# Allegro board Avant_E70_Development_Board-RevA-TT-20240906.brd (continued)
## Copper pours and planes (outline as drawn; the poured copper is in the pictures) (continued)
VCC_AUX on L12-SIG4: 72.96,83.32 73.8,84.17 74.37,84.17 74.93,83.6 75.27,83.6 75.51,83.36 75.51,81.32 76.34,80.5 80.02,80.5 80.82,81.3 80.82,95.38 82.03,96.58 82.03,99.48 83.12,100.57 83.12,120.76 83.82,121.46 100.97,121.46 101.85,120.57 101.85,115.74 100.33,114.22 91.69,114.22 90.3,112.82 90.3,103.81 90.68,103.42 90.68,91.99 84.71,86.03 84.71,78.79 81.38,75.45 73.7,75.45 72.96,76.19
VCC_AUX_IN on BOTTOM: 98.04,119.93 101.09,119.93 101.47,119.55 101.47,118.03 101.09,117.65 97.92,117.65 97.79,117.78 97.79,119.68
VCC_CORE on TOP: 107.42,94.07 107.41,94.06 106.71,94.06 106.43,93.77 106.43,86.91 106.68,86.66 119.51,86.66 119.76,86.91 119.76,93.77 119.46,94.07
VCC_CORE on BOTTOM: 75.06,75.1 74.93,75.23 74.04,75.23 73.79,75.48 73.79,79.29 74.55,80.06 74.55,81.71 75.95,83.1 80.52,83.1 82.04,84.63 82.04,92.63 83.19,93.77 100.58,93.77 103.25,91.11 106.17,91.11 106.43,91.36 106.43,93.77 106.63,93.97 114.35,93.97 114.55,93.77 114.55,91.11 112.9,89.45 112.14,89.45 110.49,87.8 98.81,87.8 92.84,81.83 89.92,81.83 89.15,81.07 89.15,79.68 88.14,78.66 87.38,78.66 86.61,77.9 86.61,77.14 86.36,77.14 86.36,75.74 85.72,75.1 ; 5 cut-outs
VCC_CORE on L03-SIG1: 114.68,94.03 107.44,94.03 107.19,93.77 107.19,89.84 107.44,89.58 114.55,89.58 114.94,89.96 114.94,93.77
VCC_CORE on L07_POW1: 75.32,77.14 75.32,89.91 75.32,89.91 75.32,92.56 77.04,94.28 77.22,94.28 77.85,94.92 111.12,94.92 111.76,94.28 114.17,94.28 114.55,93.9 114.55,91.11 111.89,88.44 111.89,86.03 111.38,85.52 107.19,85.52 105.79,84.12 105.79,64.44 104.52,63.17 78.74,63.17 77.85,64.05 77.85,75.1 77.72,75.23 74.68,75.23 74.55,75.36 74.55,76.37 74.55,76.37
VCC_DDR on TOP: 92.33,117.78 92.33,119.3 92.71,119.68 96.65,119.68 96.9,119.43 96.9,117.78 96.52,117.39 92.71,117.39
VCC_DDR on BOTTOM: 124.4,92.95 124.27,93.07 124.27,95.11 124.4,95.23 126.05,95.23 126.17,95.11 126.17,93.07 126.05,92.95
VCC_DDR on L07_POW1: 106.81,84.5 106.81,60.63 107.44,59.99 122.17,59.99 124.21,62.02 124.21,89.71 126.62,92.12 126.62,94.79 126.24,95.17 123.44,95.17 122.17,96.44 122.17,100.88 121.28,101.77 116.84,101.77 102.24,116.38 99.31,116.38 96.39,119.3 93.6,119.3 91.82,117.52 91.82,97.2 93.6,95.42 111.25,95.42 112.4,94.28 112.4,85.52 112.01,85.14 107.44,85.14
VCC_DDR_VDD1 on BOTTOM: 119.51,88.95 119.38,89.07 116.97,89.07 116.59,88.69 116.59,87.3 116.71,87.17 119.38,87.17 119.51,87.3
VCC_DDR_VDD1 on L08-POW2: 112.78,88.57 107.95,83.74 107.95,58.85 108.84,57.96 123.32,57.96 124.97,59.61 124.97,84.12 120.52,88.57
VCCA_PLL4 on TOP: 115.19,109.77 118.62,109.77 119.25,109.14 119.25,106.73 119,106.47 114.81,106.47 114.81,109.39
VCCA_PLL4 on BOTTOM: 114.94,110.41 114.94,107.36 115.32,106.98 117.86,106.98 118.24,107.36 118.24,109.52 117.35,110.41
VCCA_PLL4 on L10-SIG3: 77.77,76.11 77.77,77.99 78.76,78.98 80.95,78.98 81.54,79.57 81.54,86.9 85.58,90.93 103.56,90.93 106.48,93.85 106.48,97.25 113.41,104.19 113.41,105.33 113.92,105.84 117.09,105.84 117.6,106.35 117.6,109.52 117.22,109.9 111.51,109.9 106.17,104.57 104.52,104.57 102.41,102.46 102.41,97.71 100.46,95.76 100.46,94.61 99.95,94.1 98.56,94.1 98.32,94.35 83.66,94.35 77.91,88.6 77.91,82.61 77.25,81.96 76.48,81.96 75.44,80.92 75.44,75.87 75.63,75.68 77.34,75.68
VCCA_PLL4_IN on BOTTOM: 110.49,108.76 110.49,107.11 110.74,106.85 113.79,106.85 114.05,107.11 114.05,110.28 113.79,110.54 113.28,110.54 111.89,109.14 110.87,109.14
VCCA_PLL7 on TOP: 115.06,105.08 119,105.08 119.25,104.82 119.25,101.77 119,101.52 115.06,101.52 114.81,101.77 114.81,104.82
VCCA_PLL7 on BOTTOM: 115.06,106.09 115.06,102.41 115.44,102.03 118.11,102.03 118.24,102.15 118.24,105.96 117.98,106.22 115.19,106.22
VCCA_PLL7 on L10-SIG3: 103.96,90.58 85.85,90.58 82.18,86.91 82.18,79.75 81.1,78.68 78.9,78.68 78.15,77.93 78.15,76.78 78.59,76.35 83.23,76.35 83.68,76.79 83.68,79.36 84.64,80.32 84.64,86.02 86.52,87.9 111.73,87.9 113.86,90.03 113.86,98.54 117.98,102.66 117.98,104.95 117.35,105.58 114.3,105.58 113.66,104.95 113.66,103.81 108.12,98.26 108.12,98.22 107.06,97.16 107.06,97.07 106.81,96.82 106.81,93.43
VCCA_PLL7_IN on BOTTOM: 114.3,102.79 113.79,102.28 110.87,102.28 110.49,102.66 110.49,105.84 111,106.35 114.17,106.35 114.3,106.22
VCCA_PLL10 on TOP: 106.55,53.64 106.55,47.67 106.81,47.42 109.47,47.42 109.6,47.54 109.6,50.59 109.09,51.1 109.09,53.51 108.84,53.77 106.68,53.77
VCCA_PLL10 on BOTTOM: 86.92,75.54 86.92,71.62 87.95,70.6 87.95,69.58 90.04,67.48 90.04,65.88 91.11,64.82 91.11,62.05 97.28,55.88 104.75,55.88 106.93,53.69 106.93,51.35 107.16,51.13 108.66,51.13 108.76,51.23 108.76,53.84 105.38,57.22 98.98,57.22 93.8,62.4 93.8,67.89 93.78,67.92 93.78,69.82 92.61,70.99 90.91,70.99 89.79,72.11 89.79,75.41 89.5,75.7 88.66,75.7 88.11,76.25 87.22,76.25 87.21,76.23 86.83,76.23 86.66,76.07 86.66,75.79
VCCA_PLL10_IN on TOP: 109.98,51.74 109.98,47.67 110.24,47.42 111.89,47.42 112.27,47.8 112.27,49.58 111.76,50.08 111.76,51.74 111.63,51.86 110.11,51.86
VCCA_PLLW on TOP: 101.13,96.66 101.13,96.21 100.84,95.91 100.84,93.44 100.75,93.35 98.82,93.35 98.69,93.47 98.69,99.41 99.23,99.95 102.37,99.95 102.54,99.79 102.54,98.07
VCCA_PLLW on BOTTOM: 98.76,94.49 99.95,94.49 99.97,94.51 101.07,94.51 101.35,94.79 101.35,96.57 102.24,97.46 102.24,99.36 101.85,99.74 98.93,99.74 98.66,99.47 98.66,94.59
VCCA_PLLW on L10-SIG3: 74.5,84.17 75.07,84.74 75.07,91.96 79.95,96.84 79.95,101 81.33,102.38 98.85,102.38 98.87,102.35 101.56,102.35 101.99,101.91 101.99,97.79 100.13,95.93 100.13,94.63 99.98,94.48 98.64,94.48 98.34,94.78 83.36,94.78 77.38,88.79 77.38,83.65 77.22,83.49 74.8,83.49 74.5,83.79
VCCA_PLLW_IN on TOP: 101.73,93.16 104.51,93.16 104.76,93.41 104.76,94.41 104.66,94.51 101.64,94.51 101.6,94.46 101.6,93.29
VCCA_PLLW_IN on L12-SIG4: 102.69,99.47 106.9,99.47 107.32,99.04 107.32,93.21 106.61,92.51 102.31,92.51 102.04,92.77 102.04,98.82
VCCIO0 on TOP: 46.14,102.11 46.14,108.37 46.52,108.75 47.99,108.75 48.28,108.46 48.28,102.08 48.16,101.97 46.28,101.97
VCCIO0 on L12-SIG4: 64.52,79.04 53.39,79.04 48.56,83.87 48.56,98.15 45.91,100.8 45.91,108.58 46.51,109.18 52.89,109.18 53.46,108.61 53.46,85.77 56.76,82.47 67.82,82.47 68.39,83.04 68.39,84.95 68.87,85.42 73.11,85.42 73.97,86.28 75.23,86.28 75.38,86.14 75.38,84.46 75.3,84.37 73.77,84.37 72.63,83.24 72.63,79.03 72.26,78.66 64.9,78.66
VCCIO1 on TOP: 90.56,105.46 92.75,105.46 94.13,106.84 95.54,106.84 95.77,106.61 95.77,103.01 94.75,101.99 90.6,101.99 90.36,102.23 90.36,105.26
VCCIO1 on BOTTOM: 77.22,98.73 78.33,98.73 78.64,99.03 79.53,99.03 79.65,98.9 79.65,97.25 79.53,97.13 77.24,97.13 77.14,97.23 77.14,98.65
VCCIO1 on L10-SIG3: 70.83,84.46 69.98,85.31 69.52,85.31 69.29,85.54 69.29,99.95 75.27,105.93 75.27,109.35 75.61,109.69 99.53,109.69 100.08,109.14 100.08,103.93 99.04,102.9 80.98,102.9 79.32,101.25 79.32,97.18 74.45,92.31 74.45,84.94 73.97,84.46
VCCIO1_IN on TOP: 90.58,106.17 90.55,106.2 90.55,110.21 90.89,110.55 95.68,110.55 95.86,110.37 95.86,107.64 95.58,107.36 94.01,107.36 92.82,106.17
VCCIO1_IN on BOTTOM: 56.13,137.21 59.82,137.21 60.07,137.46 60.07,139.24 59.94,139.37 56.01,139.37 55.88,139.24 55.88,137.46
VCCIO1_IN on L05-SIG2: 49.49,129.3 46.61,126.41 46.61,120.06 45.59,119.05 45.59,116.76 48.5,113.85 50.18,113.85 50.7,113.33 59,113.33 59.74,114.07 59.74,120.24 61.34,121.84 61.34,124.58 60.58,125.35 60.58,134.62 60.56,134.64 60.56,138.25 59.94,138.86 50.16,138.86 49.49,138.19
VCCIO1_IN on L10-SIG3: 55.78,137.08 56.15,136.71 59.93,136.71 61.46,135.19 152.28,135.19 157.48,140.38 157.48,146 155.63,147.85 64.49,147.85 60.58,143.94 58.29,143.94 55.78,141.42
VCCIO1_IN on L12-SIG4: 132.21,100.76 155.85,100.76 156.21,100.39 163.47,100.39 164.19,101.11 164.19,146.32 161.07,149.44 136.44,149.44 135.42,148.42 135.42,145.27 137.66,143.02 144.93,143.02 145.1,142.86 151.57,142.86 153.29,141.14 153.29,123.21 147.09,117.01 128.02,117.01 125.6,114.6 101.47,114.6 100.71,113.84 91.88,113.84 91.44,113.4 91.31,113.4 90.68,112.76 90.68,106.73 91.19,106.22 101.85,106.22 102.36,106.73 106.04,106.73 106.55,106.22 110.36,106.22 111.51,105.08 127.89,105.08
VCCIO2 on TOP: 58.29,86.64 56.87,86.64 56.54,86.3 56.54,81.05 56.77,80.82 58.29,80.82 58.67,81.2 58.67,86.25
VCCIO2 on BOTTOM: 64.7,82.49 67.45,82.49 67.53,82.56 67.53,83.09 67.41,83.22 64.75,83.22 64.62,83.08 64.62,82.57
VCCIO2 on L12-SIG4: 61.88,118.83 62.49,118.22 62.49,111.6 63.84,110.25 69.28,110.25 71.56,107.97 71.56,99.07 73.5,97.13 73.5,86.19 73,85.7 72.57,85.7 72.12,86.14 68.9,86.14 67.92,85.16 67.92,82.96 67.69,82.72 67.18,82.72 67.17,82.71 57.52,82.71 54.08,86.15 54.08,108.9 52.51,110.46 40.23,110.46 39.55,111.14 39.55,118.13 40.24,118.83
VCCIO2_IN on TOP: 55.94,86.5 55.94,82.65 55.76,82.47 54.33,82.47 53.85,82.95 53.85,86.28 54.11,86.54 55.89,86.54
VCCIO2_IN on BOTTOM: 53.59,86.41 53.59,85.64 53.47,85.52 49.15,85.52 41.27,93.39 41.27,110.16 40.2,111.24 40.2,117.71 42.04,119.55 42.04,126.41 46.61,130.98 46.61,134.16 46.48,134.29 45.34,134.29 45.21,134.16 45.21,132.63 40.26,127.68 40.26,120.44 38.42,118.6 38.42,114.16 38.35,114.09 38.35,89.96 46.35,81.96 55.5,81.96 56.01,82.47 56.01,86.28 55.63,86.66 53.85,86.66
VCCIO3 on TOP: 68.37,113.6 68.37,114.99 69.08,115.7 69.08,116.67 69.3,116.89 75.07,116.89 75.3,116.67 75.3,113.7 74.72,113.13 68.84,113.13
VCCIO3 on L08-POW2: 59.37,73.39 59.03,73.72 59.03,90.34 55.88,93.5 55.88,110.03 56.84,110.99 59.89,110.99 65.73,116.83 75.1,116.83 75.3,116.64 75.3,110.33 75.28,110.31 75.28,108.09 74.68,107.49 65.28,107.49 64.52,106.73 64.52,98.99 68.43,95.08 68.43,80.33 68.83,79.93 73.13,79.93 74.14,78.92 74.14,73.7 73.83,73.39
VCCIO3_IN on TOP: 72.38,133.14 71.88,132.63 71.88,121.71 70.74,120.57 70.72,120.57 70.72,117.92 71.01,117.63 74.94,117.63 75.02,117.7 75.02,119.17 75.18,119.34 75.18,132.89 74.94,133.14
VCCIO4 on TOP: 75.86,113.58 75.86,116.66 76.23,117.02 82.41,117.02 82.69,116.74 82.69,113.7 82.11,113.11 76.33,113.11
VCCIO4 on BOTTOM: 65.29,98.39 67.48,98.39 67.73,98.64 67.73,99.62 67.63,99.72 65.13,99.72 65.03,99.62 65.03,98.64
VCCIO4 on L07_POW1: 62.29,63.44 61.67,64.05 61.67,111.94 66.76,117.03 82.41,117.03 82.7,116.74 82.7,113.99 81.27,112.56 72.83,112.56 68.94,108.67 68.94,74.33 71.42,71.85 71.42,68.69 71.17,68.43 68.78,68.43 68.52,68.17 68.52,63.6 68.35,63.44
VCCIO4_IN on TOP: 79.47,133.14 81.5,133.14 81.51,133.12 82.45,133.12 82.68,132.89 82.68,118.03 82.27,117.63 77.17,117.63 76.97,117.83 76.97,118.99 79.37,121.4 79.37,133.04
VCCIO5 on TOP: 86.12,113.7 90.99,113.7 91.25,113.96 91.25,116.7 90.99,116.95 86.12,116.95 85.87,116.7 85.87,113.96
VCCIO5 on BOTTOM: 72.82,97.26 74.35,97.26 74.6,97.51 74.6,98.5 74.35,98.75 72.61,98.75 72.56,98.71 72.56,97.51
VCCIO5 on L07_POW1: 69.43,63.52 69.43,67.27 69.65,67.49 71.03,67.49 72.33,68.8 72.33,71.84 69.36,74.82 69.36,108.26 73.06,111.96 81.53,111.96 83.16,113.59 83.16,116.77 83.42,117.02 90.42,117.02 90.81,116.63 90.81,96.69 89.53,95.42 77.21,95.42 74.61,92.82 74.61,76.97 73.77,76.13 73.77,75.38 74.29,74.85 77.22,74.85 77.6,74.47 77.6,63.73 77.25,63.38 69.57,63.38
VCCIO5_IN on TOP: 88.74,133.14 91.57,133.14 91.82,132.89 91.82,117.9 91.38,117.46 86.3,117.46 86.3,119.06 88.64,121.4 88.64,133.04
VCCIO6 on TOP: 114.31,110.29 114.31,114.71 114.03,114.98 110.49,114.98 110.11,114.6 110.11,110.41 110.49,110.03 114.05,110.03
VCCIO6 on BOTTOM: 114.3,114.98 110.49,114.98 110.11,114.6 110.11,110.28 110.36,110.03 111.76,110.03 112.9,111.17 114.3,111.17 114.43,111.3 114.43,114.85
VCCIO6 on BOTTOM: 77.42,68.6 78.62,68.6 78.82,68.4 78.82,65.74 78.6,65.53 77.86,65.53 77.66,65.72 77.66,66.46 78,66.8 78,67.36 77.42,67.95
VCCIO6 on L08-POW2: 74.38,73.03 74.72,73.37 80.55,73.37 80.79,73.12 80.79,60.83 84.25,57.37 100.99,57.37 102.87,59.25 102.87,84.24 105.66,87.04 105.66,106.65 105.77,106.75 105.77,108.48 110.36,113.08 114.81,113.08 115.32,112.57 115.32,91.87 107.44,83.99 107.44,55.93 104.14,52.62 80.09,52.62 74.38,58.33
VCCIO6_IN on TOP: 126.68,107.2 126.68,131.04 125.71,132.01 119.4,132.01 118.51,131.12 118.51,115.76 117.86,115.11 115.32,115.11 115.06,114.85 115.06,110.41 115.25,110.22 119.19,110.22 119.95,109.46 119.95,107.87 120.62,107.2
VCCIO6_IN on BOTTOM: 50.93,49.32 60.71,49.32 62.1,47.93 62.1,45.26 73.41,33.96 105.92,33.96 107.31,35.35 109.22,35.35 109.22,33.07 108.71,32.56 72.01,32.56 57.53,47.04 50.93,47.04 50.67,47.29 50.67,49.07
VCCIO6_IN on BOTTOM: 119.89,102.79 119.63,103.04 119.63,109.39 118.24,110.79 115.44,110.79 115.06,111.17 115.06,114.98 115.57,115.49 117.86,115.49 119,116.63 119,131.11 119.51,131.62 123.57,131.62 124.08,131.11 124.08,103.04 123.82,102.79
VCCIO6_IN on L03-SIG1: 124.64,102.33 124.21,101.9 115.04,101.9 114.27,102.66 114.27,110.38 118.82,114.93 118.82,122.04 121.79,125.01 124.08,125.01 124.64,124.46
VCCIO6_IN on L03-SIG1: 111.12,40.31 111.38,40.05 111.38,33.57 111.25,33.45 106.93,33.45 106.81,33.57 106.81,40.05 107.06,40.31
VCCIO6_IN on L12-SIG4: 60.54,46.95 59.84,46.25 38.97,46.25 38.38,45.66 6.13,45.66 0.52,51.28 0.52,113.21 3.42,116.12 13.1,116.12 13.16,116.05 15.78,116.05 18.27,118.54 18.27,123.85 27.27,132.85 65.47,132.85 72.98,140.35 116.26,140.35 124.83,131.78 124.83,125.75 123.46,124.38 123.44,124.38 123.44,115.74 122.94,115.24 119.38,115.24 118.87,115.74 118.87,123.24 116.54,125.57 116.54,125.85 110.04,132.35 73.57,132.35 64.39,123.18 36.26,123.18 31.64,118.55 31.64,117 21.29,106.65 5.71,106.65 4.61,105.55 4.61,63.17 14.29,53.48 18.3,53.48 19.91,55.09 58.73,55.09 60.54,53.28
VCCIO7 on TOP: 103.92,115.74 108.79,115.74 109.04,115.99 109.04,118.73 108.79,118.98 103.92,118.98 103.66,118.73 103.66,115.99
VCCIO7 on BOTTOM: 80.21,73.86 81.03,73.86 81.36,73.53 84.71,73.53 87.53,70.71 87.53,66.53 86.56,65.57 86.07,65.57 86.06,65.58 85.34,65.58 85.09,65.32 83.69,65.32 83.44,65.58 82.8,65.58 82.69,65.69 82.69,69.6 82.68,69.62 82.42,69.62 82.42,69.9 80.04,72.28 80.04,73.68
VCCIO7 on L05-SIG2: 82.55,70.68 83.07,70.16 83.07,68.75 83.06,68.75 82.8,68.5 81.28,68.5 80.77,69.01 80.77,78.58 82.12,79.93 82.12,80.03 82.42,80.34 82.42,97.61 85.5,100.69 85.5,100.7 88.01,103.21 88.01,118.92 88.77,119.68 108.33,119.68 109.47,118.54 109.47,112.31 108.97,111.81 101.35,111.81 99.57,110.03 99.57,102.98 87.44,90.85 87.44,81.64 85.53,79.74 85.53,78.72 82.55,75.74
VCCIO7_IN on TOP: 104.43,119.66 104.36,119.73 104.36,121.35 106.44,123.43 106.44,132.65 106.81,133.02 109.73,133.02 109.98,132.76 109.98,120.06 109.58,119.66
VCCIO8 on TOP: 112.68,115.74 117.55,115.74 117.8,115.99 117.8,118.73 117.55,118.98 112.68,118.98 112.43,118.73 112.43,115.99
VCCIO8 on BOTTOM: 97.92,60.02 100.43,60.02 100.69,60.27 100.69,61.63 100.43,61.88 97.92,61.88 97.67,61.63 97.67,60.27
VCCIO8 on L08-POW2: 84.81,57.86 81.25,61.42 81.25,73.08 81.26,73.09 81.26,74.58 81.41,74.72 84.46,74.72 84.71,74.47 84.71,72.8 85.62,71.89 89.02,71.89 89.55,71.37 89.55,68.94 91.36,67.13 91.36,62.91 92.25,62.02 97.79,62.02 98.2,62.43 98.2,93.67 97.28,94.59 97.28,100.42 98.28,101.41 98.28,112.42 102.36,116.51 102.48,116.51 102.74,116.76 102.74,116.76 104.9,118.92 116.84,118.92 117.47,118.28 117.47,114.22 116.97,113.71 111.51,113.71 111.44,113.65 110.11,113.65 105.54,109.08 105.54,107.74 105.29,107.5 105.29,87.4 102.36,84.46 102.36,59.36 100.86,57.86
VCCIO8_IN on TOP: 113.13,119.66 112.96,119.83 112.96,121.07 115.33,123.43 115.33,132.76 115.71,133.14 117.98,133.14 118.24,132.89 118.24,119.93 117.96,119.66
VCCIO10 on TOP: 91.8,116.78 91.72,116.7 91.72,112.79 92.07,112.44 97.03,112.44 97.28,112.7 97.28,116.51 97.01,116.78
VCCIO10 on L08-POW2: 85.67,72.46 89.15,72.46 89.79,71.82 89.79,69.13 91.82,67.1 91.82,63.17 92.46,62.53 97.03,62.53 97.54,63.04 97.54,83.71 97.52,83.72 97.52,93.66 96.77,94.41 96.77,101.52 97.66,102.41 97.66,106.6 97.6,106.66 97.6,115.93 96.9,116.63 92.33,116.63 91.31,115.62 91.31,112.48 85.79,106.96 85.79,101.46 82.83,98.5 82.83,99.61 82.83,99.6 82.83,86.32 82.84,86.31 82.84,84.47 85.47,81.83 85.47,76.18 85.35,76.05 85.35,72.78
VCCIO12 on TOP: 80.21,102.52 82.13,102.52 82.25,102.64 85.03,102.64 85.2,102.47 85.2,100.14 84.54,99.48 80.58,99.48 80.06,100 80.06,102.38
VCCIO12 on L08-POW2: 77.71,106.65 84.24,106.65 84.9,105.99 84.9,101.46 82.37,98.93 82.37,83.73 82.12,83.48 76.33,83.48 76.2,83.61 76.2,105.14
VCCIO12_IN on TOP: 134.37,136.27 134.37,135.05 134.49,134.92 138.76,134.92 138.99,135.15 138.99,137.13 135.23,137.13
VCCIO12_IN on TOP: 111.63,135.94 111.63,134.67 111.89,134.41 115.95,134.41 116.21,134.67 116.21,137.71 115.95,137.97 113.66,137.97
VCCIO12_IN on TOP: 87.72,103.26 88.39,103.93 88.39,108.89 87.76,109.52 72.77,109.52 72.26,109.01 72.26,103.93 72.93,103.26
VCCIO12_IN on BOTTOM: 85.52,103.4 88.09,105.96 88.09,120.01 89.03,120.95 91.06,120.95 91.44,121.33 91.44,128.44 92.84,129.84 116.21,129.84 116.38,130.02 116.38,138 115.69,138.69 85.55,138.69 82.04,135.17 82.04,131.36 81.72,131.05 75.37,131.05 74.93,130.6 74.93,114.98 72.26,112.3 72.26,103.9 72.76,103.4
VCCIO12_IN on L05-SIG2: 138.81,141.78 113.66,141.78 113.03,141.14 113.03,135.68 113.86,134.86 139.38,134.86 139.45,134.92 139.45,141.14
VCCIO13 on TOP: 68.5,116.85 63.88,116.85 63.59,116.57 63.59,112.19 64.47,111.3 67.12,111.3 67.79,111.98 67.79,115.11 68.58,115.89 68.58,116.77
VCCIO13 on L12-SIG4: 76.31,85.03 76.31,81.67 76.59,81.39 80.08,81.39 80.53,81.84 80.53,96.39 81.1,96.96 81.1,99.95 82.04,100.88 82.04,119.5 81.66,119.88 76.78,119.88 75.66,121.01 70.27,121.01 66.58,117.32 64.33,117.32 63.59,116.58 63.59,112.17 64.44,111.32 69.63,111.32 72.32,108.62 72.32,99.18 74.19,97.31 74.19,87.82 75.65,86.36 75.65,85.69
VCCIO14 on TOP: 64.92,106.92 66.67,106.92 66.82,107.07 70.55,107.07 70.87,106.74 70.87,104.12 70.41,103.66 65.11,103.66 64.78,103.99 64.78,106.77
VCCIO14 on L08-POW2: 65.28,107.11 65.02,106.85 65.02,100.18 69.43,95.77 69.43,80.68 69.71,80.4 75.12,80.4 75.13,80.39 75.51,80.39 75.69,80.56 75.69,106.6 75.18,107.11
VCCPLL_0V82 on TOP: 102.65,94.77 104.75,94.77 104.78,94.79 104.78,96.77 104.66,96.89 102.71,96.89 102.56,96.74 102.56,94.85
VCCPLL_0V82 on TOP: 99.94,106.82 99.91,106.84 99.91,108.24 99.79,108.37 99.79,109.97 100.21,110.39 102.59,110.39 102.75,110.24 102.75,108.08 102.16,107.49 102.16,106.84 101.35,106.84 101.33,106.82
VCCPLL_0V82 on TOP: 112.17,52.65 112.17,50.44 112.37,50.24 114,50.24 114.17,50.42 114.17,52.6 113.89,52.88 112.4,52.88
VCCPLL_0V82 on BOTTOM: 102.41,94.49 104.53,94.49 104.79,94.75 104.79,96.68 104.53,96.93 102.91,96.93 102.15,96.18 102.15,94.75
VCCPLL_0V82 on BOTTOM: 100.42,106.66 102.22,106.66 102.73,107.17 102.73,110.34 102.48,110.6 100.42,110.6 100.05,110.23 100.05,107.03
VCCPLL_0V82 on BOTTOM: 109.98,108.38 108.33,108.38 108.08,108.12 108.08,103.68 108.33,103.42 109.98,103.42 110.11,103.55 110.11,108.25
VCCPLL_0V82 on L05-SIG2: 111.53,58.06 113.46,59.99 121.54,59.99 122.3,60.75 122.3,85.52 121.16,86.66 101.73,86.66 100.08,88.31 100.08,109.77 101.22,110.92 112.01,110.92 112.59,110.35 112.59,102.6 114.81,100.38 135.51,100.38 136.42,99.47 136.42,82.71 135.5,81.79 135.46,81.79 134.87,81.2 134.87,53.13 131.82,50.08 112.29,50.08 111.53,50.85
(no net) on TOP: 148.46,78.79 148.58,78.91 148.58,80.51 148.49,80.6 141.77,80.6 141.48,80.31 141.48,79.04 141.73,78.79
(no net) on TOP: 148.49,120.85 147.3,120.85 147.27,120.82 147.27,120.16 147.3,120.14 149.15,120.14 149.32,120.3 149.32,122.01 151.53,122.01 152.36,122.85 152.36,128.08 152.14,128.3 148.29,128.3 148.06,128.07 148.06,122.6 148.53,122.13 148.53,120.89
(no net) on TOP: 142.12,108.94 147.43,108.94 147.62,109.13 147.62,112.58 147.45,112.75 142.23,112.75 142.04,112.56 142.04,109.02
(no net) on TOP: 142.16,95.73 146.48,95.73 146.69,95.93 146.69,99.23 146.38,99.54 140.9,99.54 140.59,99.23 140.59,95.68 140.84,95.42 141.86,95.42
(no net) on TOP: 128.71,95.48 128.55,95.32 128.55,92.53 128.81,92.27 134.04,92.27 134.26,92.5 134.26,95.39 134.17,95.48
(no net) on TOP: 143.37,134.37 143.21,134.21 143.21,131.41 143.46,131.16 148.7,131.16 148.92,131.38 148.92,134.28 148.83,134.37
(no net) on TOP: 148.49,135.32 147.3,135.32 147.27,135.3 147.27,134.64 147.3,134.61 149.15,134.61 149.32,134.78 149.32,136.49 151.53,136.49 152.01,136.98 152.01,141.76 151.81,141.97 148.23,141.97 148.06,141.8 148.06,137.08 148.53,136.61 148.53,135.37
(no net) on TOP: 40.77,35.61 40.51,35.86 40.51,36.75 41.02,37.26 42.16,37.26 42.29,37.38 42.29,38.91 42.67,39.29 42.67,41.58 42.16,42.08 40.06,42.08 39.81,42.34 39.81,42.41 39.5,42.72 39.5,44.43 39.15,44.78 39.15,46.2 39.43,46.48 39.43,49.58 39.23,49.78 37.14,49.78 37.09,49.83 37.09,50.6 38.46,51.97 38.46,56.31 38.48,56.31 38.73,56.56 41.02,56.56 45.98,51.6 45.98,51.59 46.5,51.07 46.5,50.01 46.47,49.98 45.41,49.98 45.31,50.07 45.31,50.31 45.08,50.54 44.58,50.54 44.38,50.74 42.27,50.74 42.15,50.62 42.15,45.28 45.97,41.45 45.97,39.29 45.85,39.16 44.83,39.16 44.07,38.4 44.07,37.51 45.09,36.5 45.09,31.67 44.2,30.78 43.05,30.78 42.93,30.91 42.93,32.18 42.8,32.3 42.8,33.83 43.31,34.34 43.31,35.48 43.18,35.61
(no net) on TOP: 126.62,24.18 127,24.56 127,26.21 127.25,26.46 129.54,26.46 129.79,26.21 129.79,20.87 129.67,20.75 127.13,20.75 127,20.87 127,22.27 126.37,22.91 123.7,22.91 123.57,23.03 123.57,24.05 123.7,24.18
(no net) on TOP: 141.79,84.38 147.1,84.38 147.29,84.57 147.29,88.02 147.11,88.2 141.9,88.2 141.71,88 141.71,84.46
(no net) on TOP: 127.47,127.99 132.78,127.99 132.97,128.18 132.97,131.63 132.79,131.8 127.58,131.8 127.38,131.61 127.38,128.07
(no net) on TOP: 21.97,21.81 27.67,21.81 28.14,21.34 28.14,15.1 27.69,14.65 22.76,14.65 22.75,14.66 21.96,14.66 21.46,15.16 21.46,21.31
(no net) on TOP: 148.16,81.56 146.96,81.56 146.94,81.53 146.94,80.87 146.96,80.84 148.82,80.84 148.98,81.01 148.98,82.72 151.19,82.72 151.68,83.21 151.68,87.99 151.47,88.2 147.9,88.2 147.73,88.03 147.73,83.31 148.2,82.84 148.2,81.6
(no net) on TOP: 124.71,30.15 124.71,25.07 124.84,24.94 125.86,24.94 125.98,25.07 125.98,26.72 126.49,27.22 126.49,27.61 126.87,27.99 128.65,27.99 129.03,27.61 130.05,27.61 130.3,27.86 130.3,30.15 130.18,30.27 124.84,30.27
(no net) on TOP: 128.88,86.18 133.45,86.18 133.64,86.37 133.64,89.82 133.46,89.99 128.91,89.99 128.91,89.96 128.65,89.71 128.65,86.41
(no net) on TOP: 122.17,30.15 122.17,26.97 123.19,25.95 123.19,24.81 123.82,24.81 123.82,26.08 124.21,26.46 124.21,30.02 123.95,30.27 122.3,30.27
(no net) on TOP: 142.19,81.14 146.12,81.14 146.77,81.8 147.99,81.8 147.99,81.8 147.99,82.65 146.92,83.71 142.09,83.71 142.03,83.65 142.03,81.3
(no net) on TOP: 133.84,96.44 132.64,96.44 132.62,96.41 132.62,95.75 132.64,95.73 134.5,95.73 134.66,95.89 134.66,97.6 136.8,97.6 136.91,97.71 136.91,102.57 136.4,103.08 133.58,103.08 133.41,102.91 133.41,98.19 133.88,97.73 133.88,96.48
(no net) on TOP: 122.17,20.11 122.17,18.33 121.92,18.08 121.41,18.08 121.03,17.7 121.03,16.81 121.16,16.68 124.08,16.68 124.21,16.81 124.21,22.14 123.82,22.53 123.32,22.53 123.32,21.26
(no net) on TOP: 143.37,105.16 143.21,105 143.21,102.2 143.46,101.95 148.7,101.95 148.92,102.17 148.92,105.07 148.83,105.16
(no net) on TOP: 127.87,124.75 131.8,124.75 132.45,125.41 133.67,125.41 133.67,125.41 133.67,126.25 132.6,127.32 127.77,127.32 127.71,127.26 127.71,124.91
(no net) on TOP: 142.11,23.16 141.73,22.78 141.73,20.75 141.6,20.62 139.19,20.62 139.06,20.75 139.06,26.59 139.19,26.72 141.6,26.72 141.73,26.59 141.73,25.07 142.37,24.43 145.03,24.43 145.16,24.3 145.16,23.29 145.03,23.16
(no net) on TOP: 127.47,113.51 132.78,113.51 132.97,113.7 132.97,117.15 132.79,117.33 127.58,117.33 127.38,117.13 127.38,113.59
(no net) on TOP: 124.71,22.53 124.71,16.94 124.97,16.68 130.18,16.68 130.3,16.81 130.3,19.99 130.05,20.24 127,20.24 126.75,20.49 126.75,22.02 126.24,22.53
(no net) on TOP: 127.47,99.26 132.78,99.26 132.97,99.45 132.97,102.9 132.79,103.08 127.58,103.08 127.38,102.88 127.38,99.34
(no net) on TOP: 146.56,27.22 146.56,29 146.81,29.26 147.57,29.26 147.7,29.38 147.7,30.15 147.57,30.27 144.65,30.27 144.53,30.15 144.53,25.19 144.91,24.81 145.41,24.81 145.41,26.08
(no net) on TOP: 133.84,110.69 132.64,110.69 132.62,110.66 132.62,110 132.64,109.98 134.5,109.98 134.66,110.14 134.66,111.85 136.87,111.85 137.36,112.34 137.36,117.13 137.15,117.33 133.58,117.33 133.41,117.16 133.41,112.44 133.88,111.97 133.88,110.73
(no net) on TOP: 148.05,92.9 146.86,92.9 146.84,92.88 146.84,92.22 146.86,92.19 148.72,92.19 148.88,92.36 148.88,94.07 151.09,94.07 151.57,94.56 151.57,99.34 151.37,99.55 147.79,99.55 147.63,99.38 147.63,94.66 148.09,94.19 148.09,92.94
(no net) on TOP: 146.56,17.19 146.56,20.37 145.54,21.38 145.54,22.53 144.91,22.53 144.91,21.26 144.53,20.87 144.53,17.32 144.78,17.06 146.43,17.06
(no net) on TOP: 142.52,134.91 146.45,134.91 147.11,135.57 148.32,135.57 148.33,135.57 148.33,136.41 147.26,137.48 142.43,137.48 142.36,137.42 142.36,135.07
(no net) on TOP: 102.38,112.57 102.38,116.92 102.32,116.99 99.29,116.99 98.68,116.38 98.68,112.95 99.06,112.57
(no net) on TOP: 128.76,83 132.52,83 133.12,83.6 134.34,83.6 134.34,83.6 134.34,84.44 133.27,85.51 128.78,85.51 128.65,85.38 128.65,83.1
(no net) on TOP: 133.84,125.16 132.64,125.16 132.62,125.14 132.62,124.48 132.64,124.45 134.5,124.45 134.66,124.62 134.66,126.33 136.87,126.33 137.36,126.82 137.36,131.6 137.15,131.81 133.58,131.81 133.41,131.64 133.41,126.92 133.88,126.45 133.88,125.21
(no net) on TOP: 33.94,18.33 33.94,22.58 34.17,22.81 38.46,22.81 38.73,22.53 38.73,17.95 38.48,17.7 34.04,17.7 33.91,17.83 33.91,18.31
(no net) on TOP: 32.44,22.31 32.44,20.79 32.82,20.41 32.82,15.09 32.51,14.78 29.24,14.78 28.86,15.16 28.86,20.46 29.14,20.74 30.94,20.74 31.11,20.91 31.11,22.31 31.18,22.37 32.37,22.37
(no net) on TOP: 129.38,82.4 129.22,82.24 129.22,79.44 129.48,79.19 134.71,79.19 134.93,79.41 134.93,82.31 134.84,82.4
(no net) on TOP: 142.52,120.43 146.45,120.43 147.11,121.09 148.32,121.09 148.33,121.09 148.33,121.94 147.26,123 142.43,123 142.36,122.94 142.36,120.6
(no net) on TOP: 143.37,119.89 143.21,119.73 143.21,116.94 143.46,116.68 148.7,116.68 148.92,116.9 148.92,119.8 148.83,119.89
(no net) on TOP: 29.68,47.45 29.68,51.07 29.92,51.3 36.48,51.3 36.75,51.03 36.75,49.7 36.98,49.47 38.58,49.47 38.73,49.32 38.73,48.43 38.61,48.31 36.58,48.31 35.94,47.67 35.94,47.16 35.81,47.04 30.09,47.04
(no net) on TOP: 142.12,138.15 147.43,138.15 147.62,138.34 147.62,141.79 147.45,141.96 142.23,141.96 142.04,141.77 142.04,138.23
(no net) on TOP: 37.83,57.88 37.83,52.5 37.36,52.03 27.38,52.03 26.8,52.6 26.8,55.67 29.33,58.2 37.51,58.2
(no net) on TOP: 127.87,110.27 131.8,110.27 132.45,110.93 133.67,110.93 133.67,110.93 133.67,111.78 132.6,112.84 127.77,112.84 127.71,112.78 127.71,110.44
(no net) on TOP: 30.08,21.08 28.7,22.45 22.94,22.45 22.94,24.38 26.29,27.73 29.93,27.73 29.93,26.25 30.05,26.13 38.35,26.13 38.48,26.01 38.48,23.92 38.35,23.8 36.55,23.8 36.02,23.26 34.34,23.26 34.19,23.41 31.09,23.41 30.89,23.21 30.89,21.13 30.84,21.08
(no net) on TOP: 134.5,83.35 133.31,83.35 133.29,83.33 133.29,82.67 133.31,82.64 135.17,82.64 135.33,82.81 135.33,84.52 137.54,84.52 138.02,85 138.02,89.79 137.82,90 134.24,90 134.08,89.83 134.08,85.11 134.54,84.64 134.54,83.39
(no net) on TOP: 128.71,124.21 128.55,124.05 128.55,121.25 128.81,121 134.04,121 134.26,121.22 134.26,124.12 134.17,124.21
(no net) on TOP: 148.49,106.11 147.3,106.11 147.27,106.09 147.27,105.43 147.3,105.4 149.15,105.4 149.32,105.57 149.32,107.28 151.53,107.28 152.01,107.77 152.01,112.55 151.81,112.76 148.23,112.76 148.06,112.59 148.06,107.87 148.53,107.4 148.53,106.16
(no net) on TOP: 134.09,106.83 134.26,107.01 134.26,109.64 134.17,109.73 129.16,109.73 128.86,109.44 128.86,107.11 129.14,106.83
(no net) on TOP: 142.12,123.67 147.43,123.67 147.62,123.86 147.62,128.13 147.43,128.32 142.22,128.32 142.04,128.15 142.04,123.75
(no net) on TOP: 144.02,24.81 144.02,30.02 143.76,30.27 138.56,30.27 138.43,30.15 138.43,27.48 138.81,27.1 141.73,27.1 142.11,26.72 142.11,25.19 142.49,24.81
(no net) on TOP: 127.87,96.02 131.8,96.02 132.45,96.68 133.67,96.68 133.67,96.68 133.67,97.53 132.6,98.59 127.77,98.59 127.71,98.53 127.71,96.19
(no net) on TOP: 142.93,91.95 142.77,91.79 142.77,88.99 143.03,88.74 148.26,88.74 148.48,88.96 148.48,91.86 148.39,91.95
(no net) on TOP: 144.02,22.27 143.89,22.4 142.88,22.4 142.75,22.27 142.75,20.62 142.24,20.11 142.24,19.73 141.86,19.35 140.08,19.35 139.83,19.6 138.56,19.6 138.43,19.48 138.43,16.81 138.56,16.68 143.89,16.68 144.02,16.81
(no net) on TOP: 40.77,37.89 39.37,39.29 34.16,39.29 33.53,39.92 33.53,46.35 33.8,46.62 38.83,46.62 38.95,46.51 38.95,42.72 39.96,41.7 41.91,41.7 42.16,41.45 42.16,38.15 41.91,37.89
(no net) on TOP: 142.52,105.7 146.45,105.7 147.11,106.36 148.32,106.36 148.33,106.36 148.33,107.2 147.26,108.27 142.43,108.27 142.36,108.21 142.36,105.86
(no net) on TOP: 142.09,92.49 146.02,92.49 146.67,93.15 147.89,93.15 147.89,93.15 147.89,93.99 146.82,95.06 142.13,95.06 141.98,94.91 141.98,92.6
MPM3695_SW1 on TOP: 139.57,69.26 142.75,69.26 142.88,69.13 142.88,67.99 142.75,67.86 139.57,67.86
RASP_5V on TOP: 57.12,146.45 53.11,146.45 52.73,146.07 52.73,143.1 52.1,142.46 52.1,139.44 52.6,138.93 56.34,138.93 57,139.59 57,142.41 57.78,143.2 57.78,145.79
SB_3V30 on TOP: 129.47,47.19 128.85,47.82 128.85,47.93 128.78,47.93 127.76,48.94 126.37,48.94 126.24,49.07 126.24,52.12 126.62,52.5 136.65,52.5 136.78,52.37 136.78,48.08 136.53,47.83 134.56,47.83 133.92,47.19
SB_3V30 on L03-SIG1: 137.79,78.81 151.1,78.81 151.92,78 151.92,75 151.66,74.75 150.01,74.75 149.56,75.21 146.1,75.21 145.21,76.09 143.87,76.09 142.62,74.85 142.62,55.55 135.64,48.56 126.11,48.56 125.35,49.32 125.35,55.04 126.75,56.43 129.03,56.43 136.17,63.57 136.17,77.19
SB_3V30 on L12-SIG4: 155.88,83.94 150.39,83.94 149.43,82.98 149.43,79.02 148.95,78.53 147.73,78.53 147.5,78.3 147.5,75.48 148.23,74.75 157.61,74.75 158.47,75.61 158.47,81.35
USB3_LDO_5V on TOP: 144.78,8.43 144.78,6.14 145.03,5.89 145.8,5.89 145.92,6.02 145.92,8.05 145.54,8.43
USB3_LDO_5V on TOP: 153.67,26.46 155.19,26.46 156.34,27.61 156.34,28.75 155.45,28.75 155.19,29 153.54,29 153.29,28.75 153.29,26.84
USB3_LDO_5V on BOTTOM: 144.27,8.43 145.03,8.43 145.54,7.92 145.92,7.92 146.18,8.17 146.81,8.17 146.94,8.05 146.94,6.4 146.81,6.27 144.27,6.27 144.02,6.52 144.02,8.17
USB3_LDO_5V on L03-SIG1: 114.55,12.11 115.06,11.6 135,11.6 140.84,5.76 146.69,5.76 146.81,5.89 146.81,9.32 139.95,16.18 121.79,16.18 119.51,18.46 119.51,29.76 118.75,30.53 114.94,30.53 114.55,30.15
USB3_LDO_5V on L10-SIG3: 151.13,16.18 143.64,8.68 143.64,6.27 143.89,6.02 148.72,6.02 155.83,13.13 155.83,28.62 155.45,29 152.27,29 152.02,28.75 152.02,28.62 151.13,27.73
USB_12V on TOP: 137.67,30.4 137.54,30.53 131.19,30.53 131.06,30.4 131.06,16.81 131.19,16.68 137.41,16.68 137.67,16.94
USB_12V on BOTTOM: 137.67,19.86 137.67,17.19 137.41,16.94 131.44,16.94 131.19,17.19 131.19,19.73 131.44,19.99 137.54,19.99
USB_12V on BOTTOM: 131.44,26.97 137.29,26.97 137.54,27.22 137.54,30.65 137.41,30.78 131.24,30.78 131.13,30.66 131.13,27.29
USB_12V on L12-SIG4: 140.59,30.91 122.11,30.91 120.97,29.76 120.97,17.26 122.68,15.54 160.66,15.54 161.92,16.81 161.92,37.26 161.42,37.77 142.62,37.77 141.48,36.62 141.48,31.8
USB_VBUS on TOP (solid shape): 124.21,30.02 124.21,26.46 123.82,26.08 123.82,24.81 123.19,24.81 123.19,25.95 123.09,26.05 123.09,26.12 123.02,26.12 122.17,26.97 122.17,30.15 122.3,30.27 123.95,30.27
USB_VBUS on TOP (solid shape): 145.54,21.38 145.64,21.29 145.64,21.22 145.71,21.22 146.56,20.37 146.56,17.19 146.43,17.06 144.78,17.06 144.53,17.32 144.53,20.87 144.91,21.26 144.91,22.53 145.54,22.53
USB_VBUS on TOP (solid shape): 123.89,22.46 123.89,21.22 124.21,21.22 124.21,16.81 124.08,16.68 121.16,16.68 121.03,16.81 121.03,17.7 121.41,18.08 121.67,18.08 121.92,18.08 122.17,18.33 122.17,20.06 123.27,21.16 123.27,21.21 123.32,21.26 123.32,22.53 123.82,22.53
USB_VBUS on TOP (solid shape): 147.7,30.15 147.7,29.38 147.57,29.26 147.01,29.26 146.81,29.26 146.56,29 146.56,27.27 145.46,26.17 145.46,26.13 145.41,26.08 145.41,24.81 144.91,24.81 144.84,24.87 144.84,26.12 144.53,26.12 144.53,30.15 144.65,30.27 147.57,30.27
USB_VBUS on TOP: 157.61,28.75 159.13,28.75 159.51,29.13 160.4,29.13 160.53,29 160.53,24.81 160.27,24.56 158.88,24.56 158.62,24.81 158.62,26.97 157.61,27.99
USB_VBUS on BOTTOM: 123.82,30.4 123.82,27.48 123.7,27.35 122.05,27.35 121.92,27.48 121.92,30.4 122.05,30.53 123.7,30.53
USB_VBUS on BOTTOM: 123.76,20.56 122.36,20.56 122.24,20.43 122.24,17.38 122.49,17.13 123.63,17.13 123.89,17.38 123.89,20.43
USB_VBUS on BOTTOM: 144.54,29.49 144.54,17.43 144.78,17.19 146.94,17.19 147.07,17.32 147.07,30.02 146.94,30.15 144.65,30.15 144.53,30.02 144.53,29.51
USB_VBUS on L03-SIG1: 121.16,30.4 121.16,18.21 122.17,17.19 140.46,17.19 146.05,11.6 159.64,11.6 161.42,13.38 161.42,30.4 160.27,31.54 122.3,31.54
VFMC1_3V30 on TOP (solid shape): 37.83,57.88 37.83,54.99 37.83,54.99 37.83,54.38 37.83,54.38 37.83,53.59 37.78,53.54 37.78,53.03 37.83,52.98 37.83,52.5 37.36,52.03 27.38,52.03 26.8,52.6 26.8,55.67 29.33,58.2 37.51,58.2
VFMC1_3V30 on TOP: 13.38,58.41 13.91,58.95 14.16,58.95 14.16,59.76 13.9,60.02 13.84,60.02 13.41,60.45 13.41,60.82 13.59,61 14,61 14.58,60.42 14.58,58.89 14.6,58.87 14.6,57.56 14.97,57.19 15.17,57.19 15.96,56.39 15.96,56.1 15.77,55.9 15.45,55.9 15.2,56.15 14.71,56.15 14.58,56.02 14.58,54.8 14.36,54.57 14.12,54.57 13.36,55.33 13.36,55.66 14.21,56.51 14.21,57.14 13.38,57.97
VFMC1_3V30 on BOTTOM: 12.7,60.22 13.21,60.73 16.03,60.73 16.36,60.4 16.36,54.89 17.17,54.07 20.4,54.07 21.84,52.63 21.84,36.58 19.15,33.9 19.15,30.57 19.13,30.55 19.13,25.65 17.91,24.43 10.64,24.43 9.61,25.46 9.61,27.98 11.53,29.9 11.53,42.21 13.49,44.17 13.49,50.97 12.7,51.76
VFMC1_3V30 on BOTTOM: 27.43,58.21 35.56,58.21 36.58,57.2 37.72,57.2 37.85,57.07 37.85,55.04 36.83,54.02 36.83,52.24 36.45,51.86 27.43,51.86 26.92,52.37 26.92,57.7
VFMC1_3V30 on L03-SIG1: 14.27,60.57 18.97,60.57 20.05,59.49 37.25,59.49 37.28,59.46 40.98,59.46 42.17,58.27 42.17,27.88 41.63,27.34 34.78,27.34 32.33,24.89 10.11,24.89 9.56,25.43 9.56,36.03 10.73,37.2 26.72,37.2 27.25,37.73 27.25,51.7 26.02,52.92 14.72,52.92 14.06,53.58 14.06,60.36
VFMC1_3V30 on L12-SIG4: 14.42,53.89 17.2,53.89 17.45,54.15 17.45,60.17 17.2,60.42 14.15,60.42 13.86,60.13 13.86,54.45
VFMC1_3V30AUX on BOTTOM: 17.35,64.66 17.22,64.54 15.82,64.54 15.29,64 15.29,63.85 14.96,63.52 13.06,63.52 12.75,63.83 12.75,63.98 12.37,64.36 11.66,64.36 11.25,63.95 11.25,60.17 11.4,60.02 12.09,60.02 12.27,59.84 12.27,56.82 11.99,56.54 7.95,56.54 6.48,55.06 6.48,46.91 9.65,43.73 9.65,29.38 9.19,28.93 9.19,27.48 8.81,27.1 4.83,27.1 4.19,26.46 4.19,25.7 3.78,25.29 1.85,25.29 0.53,26.62 0.53,66.11 1.92,67.49 14.85,67.49 15.11,67.23 15.11,66.11 15.39,65.83 17.07,65.83 17.35,65.55
VFMC1_ADJ on TOP: 26.8,35.23 19.68,35.23 19.56,35.1 19.56,30.27 19.68,30.15 26.92,30.15 27.05,30.27 27.05,34.97
VFMC1_ADJ on BOTTOM: 17.78,23.54 9.91,23.54 6.73,26.72 5.33,26.72 4.57,25.95 4.57,25.57 4.19,25.19 2.29,25.19 1.02,23.92 1.02,19.6 2.22,18.4 19.37,18.4 22.73,21.76 22.73,26.97 27.05,31.29 27.05,33.96 26.29,34.72 20.83,34.72 19.68,33.57 19.68,25.45
VFMC1_ADJ on L03-SIG1: 0.98,24.76 0.59,25.14 0.59,120.5 11.4,131.3 26.81,131.3 31.55,126.56 40.15,126.56 40.51,126.21 40.51,122.6 40.03,122.12 15.77,122.12 3.42,109.78 3.42,68.12 6.86,64.69 11.7,64.69 11.7,59.75 13.46,57.99 13.46,53.41 14.77,52.1 25.16,52.1 26.21,51.06 26.21,38.82 25.55,38.16 9.96,38.16 8.76,36.96 8.76,25.78 7.73,24.76
VFMC1_ADJ on L05-SIG2: 17.63,27.25 17.02,27.86 17.02,39.67 16.26,40.43 13.33,40.43 6.22,47.54 6.22,56.69 6.65,57.11 17.57,57.11 28.32,46.36 28.32,27.76 27.81,27.25
VFMC1_ADJ on L10-SIG3: 62.17,134.56 87.88,134.56 88.54,133.9 88.54,130.75 87.69,129.9 67.3,129.9 66.38,128.98 66.38,125.35 61.34,120.32 38.34,120.32 37.34,121.32 37.34,126.28 38.1,127.04 54.6,127.04 60.95,133.38 60.99,133.38
VFMC2_3V30 on TOP (solid shape): 23.1,21.77 23.71,21.77 23.75,21.81 24.46,21.81 24.5,21.77 25.11,21.77 25.15,21.81 25.85,21.81 25.9,21.77 26.51,21.77 26.55,21.81 27.25,21.81 27.34,21.72 27.76,21.72 28.14,21.34 28.14,15.1 27.69,14.65 22.76,14.65 22.75,14.66 21.96,14.66 21.46,15.16 21.46,21.31 21.97,21.81 23.06,21.81
VFMC2_3V30 on BOTTOM: 100.08,21.26 99.95,21.13 99.95,18.72 100.2,18.46 105.92,18.46 106.04,18.59 106.04,21.13 105.92,21.26
VFMC2_3V30 on L08-POW2: 14.5,27.28 18.67,27.28 25.17,20.77 30.48,20.77 32,19.25 34.75,19.25 35.18,18.82 95.4,18.82 96.44,19.86 102.62,19.86 104.2,21.45 109.41,21.45 109.85,21 109.85,7.03 109.27,6.45 14.48,6.45 13.39,7.54 13.39,26.16
VFMC2_3V30AUX on BOTTOM: 94.36,21.76 94.36,13 95.12,12.24 103.63,12.24 104.14,12.75 104.14,17.57 104.01,17.7 101.47,17.7 101.35,17.57 101.35,16.3 101.22,16.18 98.04,16.18 97.54,16.68 97.54,19.48 96.01,21 96.01,21.76
VFMC2_3V30AUX on L03-SIG1: 1.02,24.3 8.13,24.3 8.38,24.05 8.38,16.3 9.65,15.03 9.65,14.91 38.61,14.91 43.56,9.95 82.68,9.95 91.69,18.97 95.76,18.97 96.14,18.59 96.14,15.54 87.25,6.65 10.41,6.65 5.21,11.86 1.4,11.86 0.7,12.56 0.7,23.99
VFMC2_ADJ on TOP: 41.91,35.23 34.8,35.23 34.67,35.1 34.67,30.27 34.8,30.15 42.04,30.15 42.16,30.27 42.16,34.97
VFMC2_ADJ on L10-SIG3: 7.62,5.63 4.29,8.96 4.29,24.18 4.9,24.79 14,24.79 14.03,24.75 35.62,24.75 37.21,26.34 37.21,34.34 37.72,34.84 50.29,34.84 51.94,33.19 51.94,14.52 56.26,10.21 100.58,10.21 101.98,11.6 101.98,20.11 103.51,21.65 108.83,21.65 120.27,33.08 131.39,33.08 142.87,44.56 143,44.56 149.19,50.75 149.19,59.2 150.11,60.12 150.11,67.86 149.19,68.79 149.19,98.93 154.96,104.69 154.96,125.78 152.48,128.27 132.06,128.27 130.68,129.65 95.7,129.65 95.13,130.22 95.13,133.79 95.97,134.63 160.26,134.63 164.18,130.7 164.18,41.42 150.62,27.86 150.62,16.3 139.95,5.63
N00911 on BOTTOM: 15.7,129.46 15.75,129.41 16.3,129.41 17.4,130.51 18.16,130.51 18.41,130.76 18.41,131.52 18.29,131.65 15.78,131.65 15.7,131.57
N00925 on BOTTOM: 15.88,135.59 18.03,135.59 18.16,135.46 18.16,133.55 18.03,133.43 16.51,133.43 15.88,134.06
N19901221 on TOP: 131.11,135.15 131.11,140 131.13,140.01 131.13,140.37 131.44,140.69 138.81,140.69 139.45,140.05 139.45,138.5 138.66,137.71 134.72,137.71 134.01,137 134.01,135.07 133.88,134.95 131.32,134.95
N20182036 on TOP (solid shape): 36.75,51.03 36.75,49.7 36.98,49.47 38.58,49.47 38.73,49.32 38.73,48.43 38.61,48.31 36.58,48.31 35.94,47.67 35.94,47.16 35.81,47.04 30.09,47.04 29.68,47.45 29.68,51.07 29.92,51.3 36.48,51.3
N20922301 on TOP: 108.71,134.64 110.74,134.64 110.74,134.67 110.87,134.79 110.87,135.68 113.66,138.48 115.65,138.48 115.9,138.73 115.9,140.69 115.44,141.14 108.97,141.14 108.71,140.89
N20953373 on TOP (solid shape): 32.44,22.31 32.44,20.79 32.7,20.53 32.7,20.09 32.73,19.91 32.82,19.75 32.82,15.09 32.51,14.78 29.24,14.78 28.86,15.16 28.86,20.46 29.14,20.74 29.88,20.74 29.92,20.7 31,20.7 31.27,20.97 31.27,22.37 32.37,22.37
N21123855 on L05-SIG2: 50.39,139.87 50.39,141.25 48.62,143.02 39.27,143.02 35.59,146.71 35.59,148.46 36.62,149.49 56.52,149.49 59.61,146.4 59.61,144.52 60.07,144.06 60.07,140 59.61,139.54 50.72,139.54
N21271891 on TOP (solid shape): 152.01,141.76 152.01,136.98 151.53,136.49 149.32,136.49 149.32,134.78 149.15,134.61 147.3,134.61 147.27,134.64 147.27,135.3 147.3,135.32 148.49,135.32 148.53,135.37 148.53,136.61 148.06,137.08 148.06,141.8 148.23,141.97 151.81,141.97
N21271891 on L12-SIG4: 147.19,141.02 151.64,141.02 152.27,140.38 152.27,134.67 151.76,134.16 147.19,134.16 146.56,134.79 146.56,140.38
N21279900 on TOP (solid shape): 152.01,112.55 152.01,107.77 151.53,107.28 149.32,107.28 149.32,105.57 149.15,105.4 147.3,105.4 147.27,105.43 147.27,106.09 147.3,106.11 148.49,106.11 148.53,106.16 148.53,107.4 148.06,107.87 148.06,112.59 148.23,112.76 151.81,112.76
N21279900 on L07_POW1: 148.46,112.57 151.51,112.57 152.02,112.06 152.02,105.33 151.76,105.08 148.59,105.08 148.21,105.46 148.21,112.31
N21283618 on TOP (solid shape): 151.57,99.34 151.57,94.56 151.09,94.07 148.88,94.07 148.88,92.36 148.72,92.19 146.86,92.19 146.84,92.22 146.84,92.88 146.86,92.9 148.05,92.9 148.09,92.94 148.09,94.19 147.63,94.66 147.63,99.38 147.79,99.55 151.37,99.55
N21283618 on L12-SIG4: 148.34,99.36 151.51,99.36 152.27,98.6 152.27,91.87 151.89,91.49 148.08,91.49 147.57,91.99 147.57,98.6
N21285568 on TOP (solid shape): 136.91,102.57 136.91,97.71 136.8,97.6 134.66,97.6 134.66,95.89 134.5,95.73 132.64,95.73 132.62,95.75 132.62,96.41 132.64,96.44 133.84,96.44 133.88,96.48 133.88,97.73 133.41,98.19 133.41,102.91 133.58,103.08 136.4,103.08
N21285568 on L10-SIG3: 133.86,102.92 136.91,102.92 137.41,102.41 137.41,96.19 137.03,95.8 133.98,95.8 133.35,96.44 133.35,102.41
N21287697 on TOP (solid shape): 137.36,131.6 137.36,126.82 136.87,126.33 134.66,126.33 134.66,124.62 134.5,124.45 132.64,124.45 132.62,124.48 132.62,125.14 132.64,125.16 133.84,125.16 133.88,125.21 133.88,126.45 133.41,126.92 133.41,131.64 133.58,131.81 137.15,131.81
N21287697 on BOTTOM: 135.51,131.24 138.05,131.24 138.3,130.98 138.3,127.05 138.18,126.92 136.27,126.92 135.13,128.06 135.13,130.86
N21287697 on L03-SIG1: 133.73,124.76 133.98,124.51 137.41,124.51 137.79,124.89 137.79,130.09 137.41,130.48 133.86,130.48 133.73,130.35
N21298442 on TOP (solid shape): 152.36,128.08 152.36,122.85 151.53,122.01 149.32,122.01 149.32,120.3 149.15,120.14 147.3,120.14 147.27,120.16 147.27,120.82 147.3,120.85 148.49,120.85 148.53,120.89 148.53,122.13 148.06,122.6 148.06,128.07 148.29,128.3 152.14,128.3
N21298442 on L10-SIG3: 148.46,127.55 152.27,127.55 152.78,127.05 152.78,120.19 152.4,119.81 148.34,119.81 147.95,120.19 147.95,127.05
N21300096 on TOP (solid shape): 138.02,89.79 138.02,85 137.54,84.52 135.33,84.52 135.33,82.81 135.17,82.64 133.31,82.64 133.29,82.67 133.29,83.33 133.31,83.35 134.5,83.35 134.54,83.39 134.54,84.64 134.08,85.11 134.08,89.83 134.24,90 137.82,90
N21300096 on L12-SIG4: 134.24,89.71 137.16,89.71 137.67,89.2 137.67,83.23 137.16,82.72 134.11,82.72 133.73,83.1 133.73,89.2
N21310671 on TOP (solid shape): 150.73,88.2 151.07,88.09 151.41,88.19 151.42,88.2 151.47,88.2 151.68,87.99 151.68,83.21 151.19,82.72 148.98,82.72 148.98,81.01 148.82,80.84 146.96,80.84 146.94,80.87 146.94,81.53 146.96,81.56 148.16,81.56 148.2,81.6 148.2,82.84 147.73,83.31 147.73,88.03 147.9,88.2
N21316200 on TOP (solid shape): 137.36,117.13 137.36,112.34 136.87,111.85 134.66,111.85 134.66,110.14 134.5,109.98 132.64,109.98 132.62,110 132.62,110.66 132.64,110.69 133.84,110.69 133.88,110.73 133.88,111.97 133.41,112.44 133.41,117.16 133.58,117.33 137.15,117.33
N21316200 on L10-SIG3: 137.29,117.27 133.6,117.27 133.22,116.89 133.22,110.41 133.86,109.77 137.29,109.77 137.41,109.9 137.41,117.14
N21332411 on TOP: 125.72,41.8 124.46,41.8 122.35,43.91 120.01,43.91 119.48,43.38 119.48,36.01 119.76,35.73 124.08,35.73 124.37,36.02 124.37,37.29 124.37,37.3 124.37,40.39 124.88,40.91 125.65,40.91 125.72,40.98
N21332860 on TOP: 128.85,41.52 128.11,41.52 128.11,43.7 128.65,44.24 129.88,44.24 130.09,44.03 134.58,44.03 135.27,44.72 136.3,44.72 136.47,44.54 137.91,44.54 138.12,44.33 138.12,42.2 137.19,41.26 137.19,36.66 136.77,36.24 129.27,36.24 129.12,36.39 129.12,41.26
N21332860 on BOTTOM: 136.14,37.38 136.02,37.26 129.16,37.26 128.7,37.71 128.7,48.23 128.91,48.43 133.73,48.43 136.32,51.02 141.56,51.02 141.86,50.72 141.86,49.83 141.1,49.07 141.1,42.97 140.4,42.27 136.46,42.27 136.14,41.96
N21945289 on TOP: 149.99,66.85 149.99,67.74 150.62,68.37 152.27,68.37 152.4,68.25 152.4,66.85 152.27,66.72 150.11,66.72
N21945289 on BOTTOM: 155.14,72.39 155.14,71.42 155.42,71.14 155.42,70.38 155.24,70.2 154.08,70.2 153.57,70.71 152.73,70.71 152.6,70.58 152.6,69.8 152.3,69.49 151.99,69.49 150.24,67.74 150.24,66.85 150.37,66.72 154.56,66.72 155.8,67.97 155.8,68.09 156.18,68.47 156.18,69.92 156.24,69.97 156.24,71.29 156.69,71.75 158.42,71.75 159.05,72.39 159.05,73.96 158.93,74.09 158.19,74.09 157.96,73.86 157.96,73 157.43,72.46 155.22,72.46
N21945289 on L12-SIG4: 150.5,66.98 150.5,71.55 151.64,72.69 157.99,72.69 158.24,72.44 158.5,72.44 158.62,72.31 158.62,71.29 158.24,70.91 158.24,66.98 157.99,66.72 150.75,66.72
N21945322 on TOP: 148.59,66.09 148.84,66.34 151,66.34 151.13,66.21 151.13,65.2 150.88,64.94 150.88,62.78 150.75,62.66 148.72,62.66 148.59,62.78
N21945322 on BOTTOM: 127.25,55.16 134.49,55.16 135.76,56.43 146.81,56.43 147.32,55.93 147.32,52.88 146.81,52.37 127,52.37 126.62,52.75 126.62,54.53
N21945322 on L10-SIG3: 149.48,66.09 144.78,66.09 144.27,65.58 144.27,51.48 144.78,50.97 147.7,50.97 148.84,52.12 148.84,59.48 149.61,60.24 149.61,60.75 149.73,60.88 149.73,65.83
N21945422 on TOP: 151.33,63.66 151.33,64.68 152.01,65.37 153.38,65.37 153.54,65.2 153.54,63.67 153.42,63.55 151.44,63.55
N21945422 on BOTTOM: 159.41,72.34 160.35,72.34 160.88,71.8 160.88,70.46 160.81,70.38 159.87,70.38 159.64,70.15 159.64,69.8 159.49,69.64 158.98,69.64 158.75,69.87 158.75,71.67
N21945422 on BOTTOM: 151.87,63.97 151.87,65.38 152.03,65.54 152.53,65.54 153.03,66.04 153.68,66.04 153.84,65.89 153.84,65.34 153.4,64.9 153.4,63.91 153.26,63.76 152.08,63.76
N21945422 on L12-SIG4: 158.75,66.72 158.75,70.79 159,71.04 159,71.42 159.26,71.67 160.53,71.67 161.42,70.79 161.42,63.42 160.02,62.02 151.76,62.02 151.51,62.28 151.51,65.96 151.76,66.21 158.24,66.21
N21970187 on TOP: 107.95,36.75 108.59,36.75 108.84,37 108.84,37.64 108.97,37.77 110.74,37.77 110.87,37.64 110.87,35.86 110.74,35.73 107.95,35.73 107.82,35.86 107.82,36.62
N22019660 on TOP: 138.91,45.71 139.93,45.71 140,45.79 140,46.25 140.74,46.98 140.74,47.54 140.61,47.67 139.6,47.67 138.91,46.98
N22019707 on TOP: 136.68,45.51 137.79,45.51 137.79,45.51 137.92,45.64 137.92,50.73 138.03,50.84 139.49,50.84 140.77,49.56 140.77,48.05 140.64,47.92 139.47,47.92 138.71,47.16 138.71,45 138.46,44.75 136.68,44.75 136.55,44.88 136.55,45.38
N22019773 on TOP: 138.84,45.38 138.84,44.88 138.96,44.75 141.73,44.75 141.73,44.75 142.49,44.75 142.49,44.75 142.62,44.75 142.75,44.88 142.75,45.64 143.51,46.4 143.51,49.07 143.26,49.32 141.56,49.32 141.3,49.07 141.3,47.19 140.32,46.21 140.32,45.69 140.14,45.51 138.96,45.51
N22019783 on TOP: 140.08,44.5 140.21,44.37 142.11,44.37 142.37,44.12 142.37,42.21 142.24,42.08 139,42.08 138.68,42.4 138.68,44.37 138.81,44.5
N22520437 on TOP (solid shape): 129.79,26.21 129.79,20.87 129.67,20.75 127.13,20.75 127.13,22.18 126.4,22.91 124.33,22.91 123.7,22.91 123.57,23.03 123.57,24.05 123.7,24.18 126.62,24.18 127,24.56 127,26.21 127.25,26.46 129.54,26.46
N22520459 on TOP (solid shape): 141.73,26.56 141.73,25.04 142.34,24.43 144.4,24.43 145.03,24.43 145.16,24.3 145.16,23.29 145.03,23.16 142.11,23.16 141.73,22.78 141.73,20.75 141.6,20.62 139.19,20.62 139.06,20.75 139.06,26.59 139.19,26.72 141.57,26.72
N22525321 on TOP: 148.08,58.34 154.56,58.34 155.7,57.2 155.7,42.59 155.57,42.46 145.29,42.46 145.03,42.72 145.03,48.69 147.7,51.35 147.7,57.96
N22525321 on BOTTOM: 146.3,42.97 155.26,42.97 156.08,43.8 156.08,57.45 155.45,58.09 149.35,58.09 148.84,57.58 148.84,51.48 145.29,47.93 145.29,43.99
N22531852 on TOP: 25.53,37.77 24.26,39.04 19.68,39.04 19.43,38.78 19.43,36.24 19.68,35.99 24.38,35.99 25.65,37.26 26.92,37.26 27.05,37.38 27.05,37.64 26.92,37.77
N22599585 on TOP: 40.64,37.77 39.37,39.04 34.8,39.04 34.54,38.78 34.54,36.24 34.8,35.99 39.5,35.99 40.77,37.26 42.04,37.26 42.16,37.38 42.16,37.64 42.04,37.77
N22778691 on L03-SIG1: 105.41,11.1 117.73,11.1 117.86,10.97 117.86,9.19 117.6,8.94 105.41,8.94 105.16,9.19 105.16,10.84
N22778693 on L03-SIG1: 102.36,6.78 103,6.14 117.35,6.14 117.73,6.52 117.73,7.79 117.35,8.17 105.41,8.17 104.65,8.94 104.65,12.24 104.52,12.37 102.62,12.37 102.36,12.11
N22778746 on L10-SIG3: 2.41,41.7 2.41,52.88 4.95,55.42 5.46,55.42 5.84,55.04 5.84,54.4 3.81,52.37 3.81,41.83 3.56,41.58 2.54,41.58
N22778748 on L10-SIG3: 4.83,52.37 4.83,41.83 5.08,41.58 6.1,41.58 6.48,41.96 6.48,51.74 7.75,53.01 7.75,56.18 7.37,56.56 6.6,56.56 6.22,56.18 6.22,53.77

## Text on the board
BOTTOM: LAYER:10 | BOTTOM
Ref Des/Silkscreen Bottom: A
User.Comments: CR_P2_1 | CR_1_17 | CR_P2_3 | CR_P2_4 | CR_P3_2 | CR_2_10 | CR_1_18 | CR_UNNAMED_3 | CR_UNNAMED_2 | CR_P1_1 | CR_1_24 | CR_UNNAMED_8 | CR_3_6 | CR_UNNAMED_9 | CR_UNNAMED_7 | CR_UNNAMED_5 | CR_PPP_3 | CR_PPP_2 | CR_VVVVV_1 | CR_TTTTTTTTTTTT_2 | CR_P5_1 | CR_P6_2 | CR_PPP_4 | CR_P4_1 | CR_P6_1 | CR_P5_2 | CR_P4_2 | CR_WWW_1
Ref Des/Silkscreen Top: Copyright c 2024 | SB_3V30 | 12V00 | Avant-E70 Development Board Rev A | P/N:LAV-E70-D-EVN- | M | 48 | JTAG | MSPI | ON | OFF | H | GND | PLL_0V82 | 2V50 | 1V20 | 0V82 | 0V90 | 1V00 | 1V10 | 1V35 | 1V80 | 1V50 | 3V30 | 5V00 | TCK | TMS | TDI | TDO | 3V3
DIMENSION: V-CUT
User.9: ASSEMBLY-TOP | ASSEMBLY(TOP) | ASSEMBLY DRAWING NUMBER | 1/2
User.10: ASSEMBLY-BOTTOM | ASSEMBLY(BOTTOM) | ASSEMBLY DRAWING NUMBER | 2/2 | NOTE: INSTALL 0 OHM 0603 RESISTORS AT PIN1 AND PIN3 OF U44 AND U45 BY DEFAULT.
User.25: ASSEMBLY | SECONDARY-SIDE
User.26: PRIMARY-SIDE | ASSEMBLY
User.33: L2_PWR/GND | LAYER:02
User.34: LAYER:03 | L3_SIG
User.35: LAYER:04 | L4_SIG
User.36: LAYER:05 | L5_PWR
User.37: LAYER:06 | L6_PWR
User.38: LAYER:07 | L7_SIG
User.40: LAYER:09 | L9_GND
User.41: LAYER:10 | L10
User.42: LAYER:11 | L11
User.43: LAYER:12 | L12
User.44: LAYER:13 | L13
User.45: LSCC16001_ASSY | FIGURE | SIZE | 6.0 | 8.0 | 8.01 | 10.0 | 10.01 | 12.0 | 24.72 | 35.43 | 40.0 | 72.83 | 77.0 | 106.3 | 25.59 | 50.0 | 161.0 | 47.24x23.62 | 118.11x31.5 | 37.4x25.59 | DRILL CHART: TOP to BOTTOM | ALL UNITS ARE IN MILS | TOLERANCE | +2.0/-2.0 | +3.0/-3.0 | +0.0/-0.0 | +3.0/-1.0 | +2.0/-0.0 | PLATED | NON-PLATED | QTY | 447 | 375 | 1778 | 2 | 1306 | 44 | 191 | 12 | 60 | 307 | 8 | 4 | 1 | 5 | ASSY P/N:LSCC16001_ASSY
